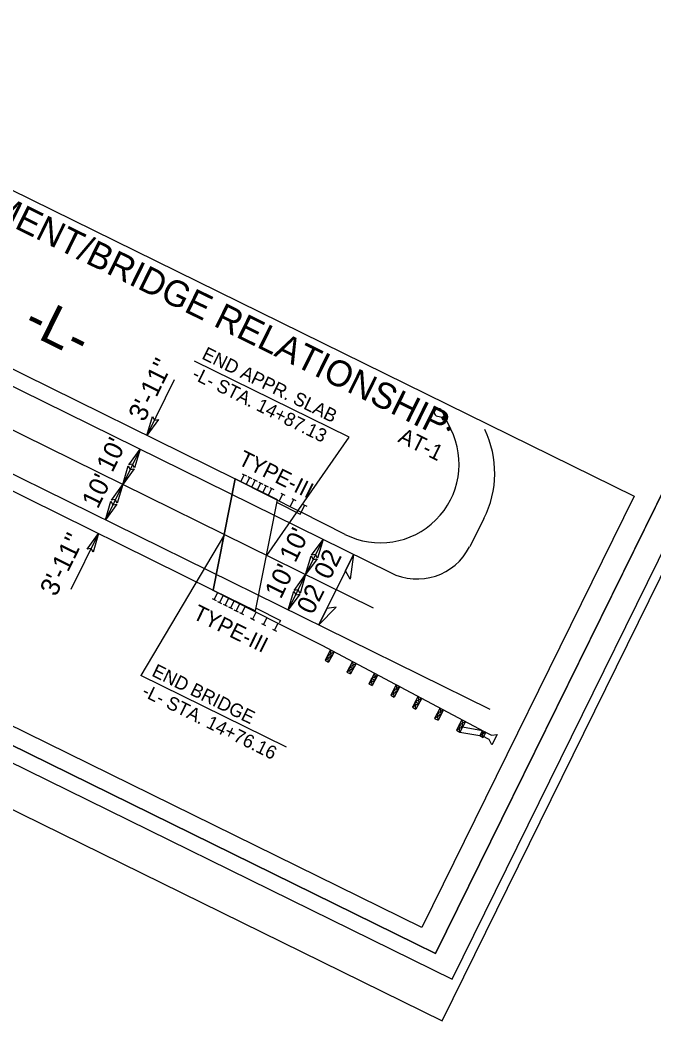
# Model space of a CAD drawing. Extents: x 1428420 to 1430540, y 857897 to 859622.
# Drawn here: x 1429729.3 to 1430031.6, y 857896.7 to 858374.2 of the extents above; entities that cross this region are included whole.
import ezdxf

# ---------------------------------------------------------------- set-up
doc = ezdxf.new("R2010")
doc.units = 0
for name, color, linetype in [('Default', 7, 'Continuous'), ('Prop Approach Slab Hatching', 7, 'Continuous'), ('Prop Conc Curb 8in x 18in', 7, 'Continuous'), ('Prop Dimension', 7, 'Continuous'), ('Prop Dimension Text', 7, 'Continuous'), ('Prop EOT', 7, 'Continuous'), ('Prop Guardrail', 7, 'Continuous'), ('Prop Guardrail Anchor Unit CELL', 7, 'Continuous'), ('Prop Horizontal Alignment', 7, 'Continuous'), ('Prop Horizontal Alignment Curve and Spiral Data', 7, 'Continuous'), ('Prop Horizontal Alignment Station Label', 7, 'Continuous'), ('Prop Roadway Bridge', 7, 'Continuous'), ('Prop Structure Anchor Unit CELL', 7, 'Continuous'), ('Prop Superelevation  Arrow CELL', 7, 'Continuous'), ('Prop Superelevation Label', 7, 'Continuous'), ('Prop Terminator CELL', 7, 'Continuous'), ('Sheet Data Text CELL', 7, 'Continuous'), ('Sheet Plan CELL', 7, 'Continuous'), ('Sheet Plot Border Inside CELL', 7, 'Continuous'), ('Sheet Plot Border Outside CELL', 7, 'Continuous')]:
    doc.layers.add(name, color=color, linetype=linetype)

msp = doc.modelspace()

# ---------------------------------------------------------------- linework, layer by layer
at = {"layer": 'Default'}
for p, q in [((1429834.6, 858153.9), (1429836.29, 858157.25)), ((1429835.33, 858157.74), (1429837.25, 858156.77)), ((1429831.99, 858155.23), (1429863.37, 858139.38)), ((1429837.22, 858152.58), (1429838.91, 858155.93)), ((1429837.95, 858156.42), (1429839.86, 858155.45)), ((1429839.83, 858151.26), (1429841.52, 858154.61)), ((1429840.56, 858155.09), (1429842.48, 858154.13)), ((1429842.45, 858149.94), (1429844.14, 858153.29)), ((1429843.18, 858153.77), (1429845.09, 858152.81)), ((1429845.06, 858148.62), (1429846.75, 858151.97)), ((1429845.79, 858152.45), (1429847.71, 858151.48)), ((1429847.68, 858147.3), (1429849.37, 858150.65)), ((1429848.41, 858151.13), (1429850.32, 858150.16)), ((1429852.91, 858144.66), (1429854.6, 858148.01)), ((1429853.64, 858148.49), (1429855.55, 858147.52)), ((1429858.14, 858142.02), (1429859.83, 858145.36)), ((1429858.87, 858145.85), (1429860.78, 858144.88)), ((1429863.37, 858139.38), (1429865.06, 858142.72)), ((1429864.1, 858143.21), (1429866.02, 858142.24))]:
    msp.add_line(p, q, dxfattribs=at)
at = {"layer": 'Prop Approach Slab Hatching'}
for p, q in [((1429831.99, 858155.23), (1429821.44, 858102.24)), ((1429852.16, 858145.24), (1429831.99, 858155.23)), ((1429841.61, 858092.25), (1429852.16, 858145.24)), ((1429821.44, 858102.24), (1429841.61, 858092.25))]:
    msp.add_line(p, q, dxfattribs=at)
at = {"layer": 'Prop Conc Curb 8in x 18in'}
for p, q in [((1429851.9, 858143.97), (1429862.94, 858138.51)), ((1429862.94, 858138.51), (1429863.49, 858139.63)), ((1429841.86, 858093.52), (1429853.5, 858087.76)), ((1429853.5, 858087.76), (1429852.94, 858086.64))]:
    msp.add_line(p, q, dxfattribs=at)
at = {"layer": 'Prop Dimension'}
for p, q in [((1429786.59, 858169.43), (1429778.31, 858152.61)), ((1429778.31, 858152.61), (1429770.03, 858135.79)), ((1429873.8, 858126.41), (1429865.53, 858109.58)), ((1429865.53, 858109.58), (1429857.25, 858092.76))]:
    msp.add_line(p, q, dxfattribs=at)
at = {"layer": 'Prop Dimension Text'}
for p, q in [((1429802.88, 858202.55), (1429789.83, 858176.02)), ((1429766.79, 858129.2), (1429753.62, 858102.45))]:
    msp.add_line(p, q, dxfattribs=at)
at = {"layer": 'Prop EOT'}
for p, q in [((1429659.35, 858232.2), (1429905.96, 858110.54)), ((1429642.76, 858198.57), (1429953.37, 858045.34)), ((1429950.54, 858136.36), (1429943.73, 858122.93))]:
    msp.add_line(p, q, dxfattribs=at)
for centre, radius, start, end in [((1429908.02, 858157.93), 47.68, 333.1111, 25.971), ((1429918.64, 858135.65), 28.12, 243.2012, 333.1111)]:
    msp.add_arc(centre, radius, start, end, dxfattribs=at)
at = {"layer": 'Prop Guardrail'}
for p, q in [((1429884.29, 858128.81), (1429863.37, 858139.38)), ((1429852.32, 858086.49), (1429873.24, 858075.92))]:
    msp.add_line(p, q, dxfattribs=at)
msp.add_arc((1429901.19, 858162.28), 37.5, 243.2012, 26.4407, dxfattribs=at)
at = {"layer": 'Prop Guardrail Anchor Unit CELL'}
for p, q in [((1429931.65, 858185.26), (1429930.29, 858184.59)), ((1429931.81, 858184.93), (1429930.38, 858187.81)), ((1429931.65, 858185.26), (1429930.87, 858183.41)), ((1429931.65, 858185.26), (1429931.05, 858184.97)), ((1429931.65, 858185.26), (1429931.05, 858184.97)), ((1429932.23, 858184.09), (1429931.65, 858185.26)), ((1429928.38, 858185.16), (1429930.61, 858184.75)), ((1429930.29, 858184.59), (1429930.87, 858183.41)), ((1429932.23, 858184.09), (1429930.29, 858184.59)), ((1429930.87, 858183.41), (1429932.23, 858184.09)), ((1429931.76, 858185.04), (1429931.87, 858184.82)), ((1429931.76, 858185.04), (1429931.87, 858184.82)), ((1429934.77, 858178.98), (1429931.81, 858184.93)), ((1429934.19, 858180.15), (1429932.83, 858179.48)), ((1429932.83, 858179.48), (1429933.42, 858178.3)), ((1429934.77, 858178.98), (1429932.83, 858179.48)), ((1429934.19, 858180.15), (1429933.42, 858178.3)), ((1429933.42, 858178.3), (1429934.77, 858178.98)), ((1429934.77, 858178.98), (1429934.19, 858180.15)), ((1429873.24, 858075.92), (1429950.68, 858034.84)), ((1429877.45, 858073.69), (1429874.81, 858068.72)), ((1429876.13, 858071.2), (1429879.11, 858072.81)), ((1429876.13, 858071.2), (1429877.79, 858070.32)), ((1429876.47, 858067.84), (1429876.13, 858071.2)), ((1429879.11, 858072.81), (1429876.47, 858067.84)), ((1429877.45, 858073.69), (1429879.11, 858072.81)), ((1429877.79, 858070.32), (1429877.45, 858073.69)), ((1429879.11, 858072.81), (1429877.79, 858070.32)), ((1429877.79, 858070.32), (1429874.81, 858068.72)), ((1429874.81, 858068.72), (1429876.47, 858067.84)), ((1429887.89, 858068.15), (1429885.2, 858063.09)), ((1429886.55, 858065.62), (1429889.54, 858067.27)), ((1429889.54, 858067.27), (1429886.86, 858062.22)), ((1429887.89, 858068.15), (1429888.2, 858064.74)), ((1429888.2, 858064.74), (1429885.2, 858063.09)), ((1429885.2, 858063.09), (1429886.86, 858062.22)), ((1429886.55, 858065.62), (1429888.2, 858064.74)), ((1429886.86, 858062.22), (1429886.55, 858065.62)), ((1429898.32, 858062.61), (1429895.65, 858057.57)), ((1429896.99, 858060.09), (1429899.98, 858061.74)), ((1429899.98, 858061.74), (1429897.3, 858056.69)), ((1429898.32, 858062.61), (1429898.64, 858059.21)), ((1429898.64, 858059.21), (1429895.65, 858057.57)), ((1429895.65, 858057.57), (1429897.3, 858056.69)), ((1429896.99, 858060.09), (1429898.64, 858059.21)), ((1429897.3, 858056.69), (1429896.99, 858060.09)), ((1429908.76, 858057.08), (1429906.09, 858052.05)), ((1429908.76, 858057.08), (1429910.42, 858056.2)), ((1429908.76, 858057.08), (1429909.08, 858053.68)), ((1429909.08, 858053.68), (1429906.09, 858052.05)), ((1429906.09, 858052.05), (1429907.75, 858051.17)), ((1429907.43, 858054.56), (1429910.42, 858056.2)), ((1429907.43, 858054.56), (1429909.08, 858053.68)), ((1429907.75, 858051.17), (1429907.43, 858054.56)), ((1429910.42, 858056.2), (1429907.75, 858051.17)), ((1429919.2, 858051.54), (1429916.44, 858046.34)), ((1429919.2, 858051.54), (1429919.48, 858048.06)), ((1429919.48, 858048.06), (1429916.44, 858046.34)), ((1429917.82, 858048.94), (1429920.86, 858050.66)), ((1429917.82, 858048.94), (1429919.48, 858048.06)), ((1429918.1, 858045.46), (1429917.82, 858048.94)), ((1429920.86, 858050.66), (1429918.1, 858045.46)), ((1429916.44, 858046.34), (1429918.1, 858045.46)), ((1429929.64, 858046), (1429927, 858041.04)), ((1429929.97, 858042.64), (1429927, 858041.04)), ((1429928.32, 858043.52), (1429931.29, 858045.13)), ((1429928.32, 858043.52), (1429929.97, 858042.64)), ((1429928.66, 858040.16), (1429928.32, 858043.52)), ((1429931.29, 858045.13), (1429928.66, 858040.16)), ((1429929.64, 858046), (1429929.97, 858042.64)), ((1429927, 858041.04), (1429928.66, 858040.16)), ((1429940.07, 858040.47), (1429937.38, 858035.39)), ((1429938.73, 858037.93), (1429941.73, 858039.59)), ((1429938.73, 858037.93), (1429940.38, 858037.05)), ((1429939.04, 858034.51), (1429938.73, 858037.93)), ((1429941.73, 858039.59), (1429939.04, 858034.51)), ((1429940.07, 858040.47), (1429940.38, 858037.05)), ((1429940.38, 858037.05), (1429937.38, 858035.39)), ((1429937.38, 858035.39), (1429939.04, 858034.51)), ((1429939.04, 858034.51), (1429948.53, 858032.8)), ((1429940.38, 858037.05), (1429949.85, 858035.28)), ((1429949.85, 858035.28), (1429948.53, 858032.8)), ((1429951.5, 858034.4), (1429948.53, 858032.8)), ((1429948.53, 858032.8), (1429949.36, 858032.36)), ((1429948.53, 858032.8), (1429950.19, 858031.92)), ((1429949.62, 858032.65), (1429950.14, 858033.67)), ((1429953.05, 858030.91), (1429949.62, 858032.65)), ((1429950.19, 858031.92), (1429949.85, 858035.28)), ((1429950.14, 858033.67), (1429950.66, 858034.69)), ((1429951.5, 858034.4), (1429950.19, 858031.92)), ((1429950.66, 858034.69), (1429954.09, 858032.95)), ((1429954.09, 858032.95), (1429956.78, 858033.39)), ((1429956.78, 858033.39), (1429954.29, 858028.48)), ((1429954.29, 858028.48), (1429953.05, 858030.91))]:
    msp.add_line(p, q, dxfattribs=at)
msp.add_ellipse((1429928.71, 858186.98), major_axis=(-1.67, -0.83), ratio=0.995379, start_param=3.141593, end_param=7.214552, dxfattribs=at)
at = {"layer": 'Prop Horizontal Alignment'}
msp.add_line((1429651.06, 858215.38), (1429897.67, 858093.73), dxfattribs=at)
at = {"layer": 'Prop Horizontal Alignment Curve and Spiral Data'}
msp.add_lwpolyline([(1429575.84, 858366.59), (1430022.18, 858146.96), (1429920.93, 857941.2), (1429474.59, 858160.83)], close=True, dxfattribs=at)
at = {"layer": 'Prop Roadway Bridge'}
for p, q in [((1429697.46, 858221.59), (1429831.99, 858155.23)), ((1429686.92, 858168.6), (1429821.44, 858102.24)), ((1429821.44, 858102.24), (1429831.99, 858155.23))]:
    msp.add_line(p, q, dxfattribs=at)
at = {"layer": 'Prop Structure Anchor Unit CELL'}
for p, q in [((1429820.94, 858102.34), (1429852.32, 858086.49)), ((1429823.55, 858101.02), (1429821.86, 858097.67)), ((1429826.17, 858099.7), (1429824.48, 858096.35)), ((1429820.9, 858098.15), (1429822.82, 858097.19)), ((1429823.52, 858096.83), (1429825.44, 858095.87)), ((1429826.13, 858095.51), (1429828.05, 858094.54)), ((1429828.78, 858098.38), (1429827.09, 858095.03)), ((1429831.4, 858097.06), (1429829.71, 858093.71)), ((1429834.01, 858095.73), (1429832.32, 858092.39)), ((1429828.75, 858094.19), (1429830.67, 858093.22)), ((1429831.36, 858092.87), (1429833.28, 858091.9)), ((1429833.98, 858091.55), (1429835.9, 858090.58)), ((1429836.63, 858094.41), (1429834.94, 858091.07)), ((1429841.86, 858091.77), (1429840.17, 858088.42)), ((1429839.21, 858088.91), (1429841.13, 858087.94)), ((1429844.44, 858086.27), (1429846.36, 858085.3)), ((1429847.09, 858089.13), (1429845.4, 858085.78)), ((1429852.32, 858086.49), (1429850.63, 858083.14)), ((1429849.67, 858083.63), (1429851.59, 858082.66))]:
    msp.add_line(p, q, dxfattribs=at)
at = {"layer": 'Prop Superelevation  Arrow CELL'}
for p in [(1429888.33, 858119.24), (1429871.78, 858085.59)]:
    msp.add_line(p, (1429880.06, 858102.42), dxfattribs=at)
for points in [[(1429888.33, 858119.24), (1429886.73, 858107.49), (1429884.51, 858111.46)], [(1429871.78, 858085.59), (1429880.11, 858094.03), (1429875.61, 858093.37)]]:
    msp.add_lwpolyline(points, close=True, dxfattribs=at)
at = {"layer": 'Prop Terminator CELL'}
for points in [[(1429795.34, 858183.62), (1429789.83, 858176.02), (1429792.46, 858185.1), (1429793.41, 858183.31)], [(1429781.15, 858161.95), (1429786.59, 858169.43), (1429783.99, 858160.5), (1429783.05, 858162.26)], [(1429783.74, 858160.09), (1429778.31, 858152.61), (1429780.9, 858161.55), (1429781.84, 858159.79)], [(1429772.88, 858145.13), (1429778.31, 858152.61), (1429775.72, 858143.67), (1429774.78, 858145.43)], [(1429775.46, 858143.27), (1429770.03, 858135.79), (1429772.62, 858144.72), (1429773.56, 858142.96)], [(1429761.36, 858121.71), (1429766.79, 858129.2), (1429764.19, 858120.26), (1429763.26, 858122.02)], [(1429868.37, 858118.92), (1429873.8, 858126.41), (1429871.21, 858117.47), (1429870.27, 858119.23)], [(1429870.96, 858117.07), (1429865.53, 858109.58), (1429868.12, 858118.52), (1429869.06, 858116.76)], [(1429860.1, 858102.1), (1429865.53, 858109.58), (1429862.93, 858100.65), (1429862, 858102.41)], [(1429862.68, 858100.24), (1429857.25, 858092.76), (1429859.84, 858101.7), (1429860.78, 858099.94)]]:
    msp.add_lwpolyline(points, close=True, dxfattribs=at)
at = {"layer": 'Sheet Data Text CELL'}
for p, q in [((1429886.31, 858175.1), (1429812.54, 858211.4)), ((1429846.95, 858118.75), (1429886.31, 858175.1)), ((1429826.76, 858128.71), (1429786.95, 858061.51)), ((1429856.41, 858027.33), (1429786.95, 858061.51))]:
    msp.add_line(p, q, dxfattribs=at)
at = {"layer": 'Sheet Plan CELL'}
for points in [[(1430386.67, 858862), (1429040.75, 859524.27), (1428581.58, 858591.12), (1429927.48, 857928.86)], [(1428581.58, 858591.12), (1429040.71, 859524.26), (1430207.15, 858950.35), (1430140.91, 858815.69), (1430320.39, 858727.37), (1429927.48, 857928.86)]]:
    msp.add_lwpolyline(points, close=True, dxfattribs=at)
at = {"layer": 'Sheet Plot Border Inside CELL'}
msp.add_lwpolyline([(1428440.55, 858652.15), (1429935.37, 857916.62), (1430401.17, 858863.21), (1428906.33, 859598.76)], close=True, dxfattribs=at)
at = {"layer": 'Sheet Plot Border Outside CELL'}
msp.add_lwpolyline([(1428420.05, 858639.94), (1429930.59, 857896.67), (1430414.03, 858879.17), (1428903.5, 859622.44)], close=True, dxfattribs=at)

# ---------------------------------------------------------------- texts
at = {"layer": 'Prop Dimension Text'}
for s, p in [("3'-11''", (1429788.6, 858182.09)), ("10'", (1429773.37, 858157.9)), ("10'", (1429766.42, 858140.6)), ("3'-11''", (1429746.45, 858098.73)), ("10'", (1429860.59, 858114.87)), ("10'", (1429853.64, 858097.57))]:
    msp.add_text(s, height=9, rotation=63.8001, dxfattribs=at).set_placement(p)
at = {"layer": 'Prop Guardrail Anchor Unit CELL'}
for s, p in [('AT-1', (1429909.12, 858173.19)), ('TYPE-III', (1429832.86, 858162.43)), ('TYPE-III', (1429811.17, 858088.85))]:
    msp.add_text(s, height=7.5, rotation=333.8001, dxfattribs=at).set_placement(p)
at = {"layer": 'Prop Horizontal Alignment Station Label'}
for s, height, p in [('SKETCH OF PAVEMENT/BRIDGE RELATIONSHIP', 12.375, (1429585.13, 858344.55)), ('-L-', 18.75, (1429729.91, 858226.04))]:
    msp.add_text(s, height=height, rotation=333.8001, dxfattribs=at).set_placement(p)
at = {"layer": 'Prop Superelevation Label'}
for p in [(1429877, 858106.66), (1429868.83, 858090.07)]:
    msp.add_text('02', height=9, rotation=63.3554, dxfattribs=at).set_placement(p)
at = {"layer": 'Sheet Data Text CELL'}
for s, p in [('END APPR. SLAB', (1429815.58, 858212.8)), ('-L- STA. 14+87.13', (1429810.89, 858203.27)), ('END BRIDGE', (1429791.69, 858061.52)), ('-L- STA. 14+76.16', (1429787, 858051.98))]:
    msp.add_text(s, height=6.375, rotation=333.8001, dxfattribs=at).set_placement(p)

doc.saveas('drawing.dxf')
